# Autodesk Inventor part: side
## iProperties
Created: 2008-04
Part Number: side
Document SubType Name: Modeling
Designer: Jayson Martinez
Density: 1 g/cm^3
Author: Jayson Martinez
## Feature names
1. Extrusion1
